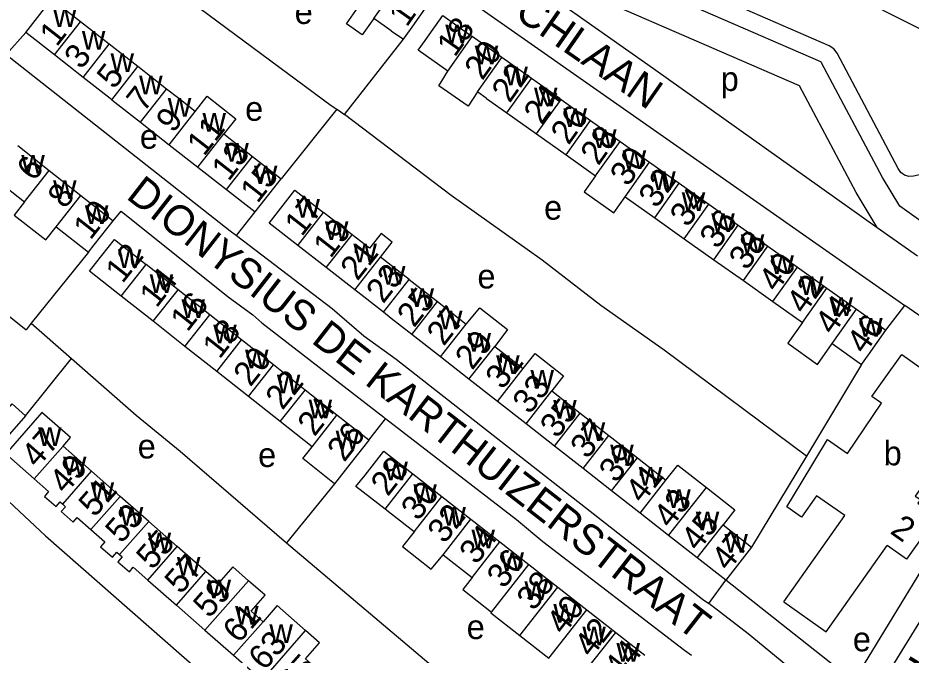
# Model space of a CAD drawing. Extents: x 162804 to 165059, y 381530 to 382901.
# Drawn here: x 162938.5 to 163085.6, y 381908.3 to 382013.3 of the extents above; entities that cross this region are included whole.
import ezdxf

# ---------------------------------------------------------------- set-up
doc = ezdxf.new("R2010")
doc.units = 0
for name, color, linetype in [('BLT_Basislijn', 7, 'Continuous'), ('BLT_Bebouwing', 7, 'Continuous'), ('BLT_Centroide', 7, 'Continuous'), ('BLT_Huisnummer', 7, 'Continuous'), ('BLT_Huisnummer_ tussenligend', 7, 'Continuous'), ('BLT_Onderverdeling_panden', 7, 'Continuous'), ('BLT_Straatnaam', 7, 'Continuous')]:
    doc.layers.add(name, color=color, linetype=linetype)

msp = doc.modelspace()

# ---------------------------------------------------------------- linework, layer by layer
at = {"layer": 'BLT_Basislijn'}
for p, q in [((163017.7, 382022.93), (163043.15, 382004.93)), ((162939.82, 382010.89), (162936.61, 382007.27)), ((162992.27, 381997.38), (163002.01, 382009.76)), ((162991.04, 381998.28), (162981.87, 381986.8)), ((162974.48, 381977.48), (162977.59, 381981.33)), ((162950.13, 381974.7), (162940.71, 381963)), ((163081.43, 381961.88), (163084.55, 381965.91)), ((163104.58, 381951.95), (163084.55, 381965.91)), ((162940.71, 381963), (162939.87, 381961.94)), ((162939.79, 381947.76), (162947.33, 381957.19)), ((163077.42, 381956.21), (163068.32, 381941.11)), ((162996.28, 381943.74), (162999.06, 381947.28)), ((163068.32, 381941.11), (163059.3, 381926.12)), ((162990.63, 381936.58), (162982.74, 381926.86)), ((162982.74, 381926.86), (163031.79, 381885.39)), ((163052.24, 381916.83), (163055.05, 381920.69))]:
    msp.add_line(p, q, dxfattribs=at)
for points in [[(163069.06, 382020.59), (163092.61, 382008.67), (163093.4, 382008.13), (163093.97, 382007.5), (163094.42, 382006.7), (163094.66, 382005.84), (163095.46, 381992), (163095.33, 381990.1), (163094.6, 381989.08), (163085.95, 381987.21), (163085.18, 381987.15), (163084.46, 381987.37), (163083.85, 381987.84), (163083.46, 381988.49), (163073.39, 382007.47), (163072.87, 382008.21), (163072.1, 382008.69), (163021.58, 382030.69)], [(163083.72, 381982.26), (163080.85, 381987.02), (163070.82, 382005.91), (163070.76, 382005.99), (163070.7, 382006.03), (163017.52, 382029.19)], [(162952.58, 382027.08), (162967.07, 382015.96), (162990.08, 381998.88), (162991.04, 381998.28)], [(163079.98, 381978.78), (163076.5, 381984.55), (163067.17, 382002.11), (163018.09, 382023.48), (163017.7, 382022.93)], [(163008.76, 382019.07), (163083.58, 381966.59), (163084.55, 381965.91)], [(162936.61, 382007.27), (162973.48, 381978.24), (162974.48, 381977.48)], [(163043.15, 382004.93), (163079.98, 381978.78)], [(162991.04, 381998.28), (162991.3, 381998.11), (162992.27, 381997.38)], [(163068.32, 381941.11), (163044.93, 381958.57), (163034.48, 381965.9), (163024.84, 381973.39), (163009.83, 381984.04), (162992.27, 381997.38)], [(162913.43, 381984.1), (162927.71, 381972.16), (162934.84, 381965.92), (162939.87, 381961.94)], [(162954.2, 381979.85), (162955.5, 381981.48), (162973.11, 381967.38), (162977.21, 381964.39), (162978.7, 381963.05), (162998.74, 381947.53), (162999.06, 381947.28)], [(163088.69, 381978.74), (163083.72, 381982.26)], [(163079.98, 381978.78), (163086.6, 381974.08)], [(162974.48, 381977.48), (162990.26, 381965.42), (162995.48, 381960.92), (163000.81, 381957.09), (163051.25, 381917.58), (163052.24, 381916.83)], [(162940.71, 381963), (162946.88, 381957.58), (162947.33, 381957.19)], [(162947.33, 381957.19), (162957.97, 381947.89), (162965.23, 381941.96), (162982.74, 381926.86)], [(163104.58, 381951.95), (163107.72, 381949.86), (163108.33, 381948.97), (163107.96, 381947.96), (163081.42, 381904.82), (163078.3, 381900.84), (163076.07, 381900.06), (163074.79, 381900.06), (163072.4, 381900.61), (163058.73, 381911.86), (163052.24, 381916.83)], [(163104.58, 381951.95), (163102.76, 381948.29), (163098.1, 381940.15), (163076.45, 381904.65), (163075.65, 381904.65), (163073.11, 381906.41), (163055.05, 381920.69)], [(163049.39, 381908.29), (163048.27, 381909.14), (163024.93, 381927.03), (163020.58, 381930.61), (162999.06, 381947.28)], [(162933.29, 381940.41), (162931.69, 381938.6), (162943.06, 381927.99), (162971.29, 381903.26), (162975.18, 381899.34), (162996.37, 381880.88), (163016.11, 381863.18), (163017.03, 381862.36)]]:
    msp.add_lwpolyline(points, dxfattribs=at)
at = {"layer": 'BLT_Bebouwing'}
for p, q in [((162948.82, 382012.66), (162944.09, 382016.36)), ((162953.54, 382008.97), (162948.82, 382012.66)), ((162999.99, 382011.17), (162997.11, 382013.21)), ((162944.54, 382007.19), (162939.82, 382010.89)), ((162999.99, 382011.17), (163002.01, 382009.76)), ((163018.19, 382006.77), (163013.32, 382010.22)), ((162958.26, 382005.27), (162953.54, 382008.97)), ((162949.26, 382003.5), (162944.54, 382007.19)), ((163023.06, 382003.32), (163018.19, 382006.77)), ((162962.99, 382001.58), (162958.26, 382005.27)), ((163027.72, 382000.02), (163023.06, 382003.32)), ((163015.68, 382000.01), (163014.16, 382001.09)), ((162953.98, 381999.8), (162958.71, 381996.11)), ((163015.68, 382000.01), (163019.03, 381997.64)), ((163027.72, 382000.02), (163027.93, 381999.87)), ((163027.93, 381999.87), (163032.79, 381996.42)), ((163019.03, 381997.64), (163023.89, 381994.18)), ((162958.71, 381996.11), (162963.43, 381992.41)), ((163032.79, 381996.42), (163037.66, 381992.96)), ((162972.43, 381994.19), (162977.15, 381990.49)), ((163023.89, 381994.18), (163028.76, 381990.73)), ((162938.49, 381992.25), (162943.69, 381988.14)), ((162963.43, 381992.41), (162968.15, 381988.72)), ((163037.66, 381992.96), (163042.52, 381989.51)), ((162977.15, 381990.49), (162981.87, 381986.8)), ((163028.76, 381990.73), (163033.63, 381987.28)), ((162968.15, 381988.72), (162972.88, 381985.02)), ((163042.52, 381989.51), (163047.39, 381986.05)), ((162934.42, 381987.1), (162939.63, 381982.99)), ((162943.69, 381988.14), (162948.87, 381984.05)), ((163047.39, 381986.05), (163052.25, 381982.6)), ((162972.88, 381985.02), (162977.59, 381981.33)), ((162948.87, 381984.05), (162954.2, 381979.85)), ((163038.49, 381983.83), (163043.36, 381980.38)), ((162993.53, 381977.59), (162988.83, 381981.26)), ((163052.25, 381982.6), (163057.12, 381979.15)), ((163043.36, 381980.38), (163048.23, 381976.92)), ((162944.81, 381978.9), (162950.13, 381974.7)), ((163057.12, 381979.15), (163061.98, 381975.69)), ((163048.23, 381976.92), (163053.09, 381973.47)), ((162989.28, 381972.16), (162984.58, 381975.83)), ((163061.98, 381975.69), (163066.85, 381972.24)), ((162964.88, 381968.53), (162959.65, 381972.66)), ((163053.09, 381973.47), (163057.96, 381970.02)), ((162993.98, 381968.48), (162989.28, 381972.16)), ((163066.85, 381972.24), (163071.71, 381968.78)), ((163002.92, 381970.23), (163007.62, 381966.56)), ((163057.96, 381970.02), (163062.82, 381966.57)), ((162970.11, 381964.4), (162964.88, 381968.53)), ((162998.68, 381964.81), (162993.98, 381968.48)), ((163071.71, 381968.78), (163076.57, 381965.33)), ((162960.78, 381963.33), (162955.54, 381967.47)), ((163007.62, 381966.56), (163012.32, 381962.88)), ((163062.82, 381966.57), (163067.69, 381963.11)), ((163076.57, 381965.33), (163081.43, 381961.88)), ((162975.35, 381960.27), (162970.11, 381964.4)), ((162966.01, 381959.2), (162960.78, 381963.33)), ((163008.07, 381957.45), (163003.38, 381961.13)), ((162971.25, 381955.07), (162966.01, 381959.2)), ((162980.58, 381956.13), (162975.35, 381960.27)), ((163017.02, 381959.2), (163021.71, 381955.53)), ((163072.56, 381959.66), (163077.42, 381956.21)), ((163012.77, 381953.78), (163008.07, 381957.45)), ((162976.48, 381950.94), (162971.25, 381955.07)), ((162985.82, 381952), (162980.58, 381956.13)), ((163017.47, 381950.1), (163012.77, 381953.78)), ((162991.05, 381947.87), (162985.82, 381952)), ((163026.41, 381951.85), (163031.11, 381948.18)), ((162981.71, 381946.81), (162976.48, 381950.94)), ((163022.17, 381946.43), (163017.47, 381950.1)), ((162996.28, 381943.74), (162991.05, 381947.87)), ((163031.11, 381948.18), (163035.81, 381944.5)), ((162986.95, 381942.67), (162981.71, 381946.81)), ((163026.86, 381942.75), (163022.17, 381946.43)), ((163035.81, 381944.5), (163040.51, 381940.82)), ((162950.65, 381938.62), (162945.95, 381942.75)), ((163031.56, 381939.07), (163026.86, 381942.75)), ((163040.51, 381940.82), (163045.2, 381937.15)), ((162955.35, 381934.49), (162950.65, 381938.62)), ((163036.26, 381935.4), (163031.56, 381939.07)), ((163003.53, 381938.21), (163008.3, 381934.48)), ((162960.06, 381930.37), (162955.35, 381934.49)), ((163008.3, 381934.48), (163013.08, 381930.74)), ((163040.96, 381931.72), (163036.26, 381935.4)), ((163045.65, 381928.04), (163040.96, 381931.72)), ((163064.63, 381917.13), (163074.68, 381931.32)), ((162964.76, 381926.24), (162960.06, 381930.37)), ((163013.08, 381930.74), (163017.86, 381927.01)), ((163054.6, 381929.8), (163059.3, 381926.12)), ((163017.86, 381927.01), (163022.64, 381923.27)), ((163050.35, 381924.37), (163045.65, 381928.04)), ((162969.46, 381922.11), (162964.76, 381926.24)), ((163071.59, 381912.19), (163081.65, 381926.39)), ((163008.51, 381924.89), (163013.29, 381921.16)), ((163055.05, 381920.69), (163050.35, 381924.37)), ((163022.64, 381923.27), (163027.41, 381919.54)), ((162959.91, 381920.72), (162964.62, 381916.6)), ((163027.41, 381919.54), (163032.19, 381915.8)), ((162964.62, 381916.6), (162969.32, 381912.48)), ((163064.63, 381917.13), (163071.59, 381912.19)), ((163032.19, 381915.8), (163036.97, 381912.07)), ((162969.32, 381912.48), (162974.03, 381908.36)), ((163021.15, 381911.59), (163025.9, 381907.87)), ((163036.97, 381912.07), (163041.74, 381908.34)), ((162974.03, 381908.36), (162978.74, 381904.24))]:
    msp.add_line(p, q, dxfattribs=at)
for points in [[(162997.11, 382013.21), (162995.2, 382010.52), (162992.64, 382012.33), (162994.55, 382015.03), (162992.21, 382016.68)], [(162939.82, 382010.89), (162942.9, 382014.82), (162944.09, 382016.36)], [(163002.01, 382009.76), (163003.14, 382011.36), (163006.03, 382015.43)], [(163009.29, 382004.54), (163004.42, 382007.98), (163005.56, 382009.59), (163008.45, 382013.67), (163013.32, 382010.22)], [(162953.98, 381999.8), (162953.73, 382000), (162949.26, 382003.5)], [(163014.16, 382001.09), (163012.62, 381998.73), (163007.83, 382002.12), (163009.29, 382004.54)], [(162967.71, 381997.88), (162964.99, 382000.01), (162962.99, 382001.58)], [(162967.71, 381997.88), (162969.66, 382000.39), (162974.37, 381996.65), (162972.43, 381994.19)], [(163033.63, 381987.28), (163031.77, 381984.66), (163036.64, 381981.21), (163038.49, 381983.83)], [(162977.59, 381981.33), (162980.68, 381985.27), (162981.87, 381986.8)], [(162984.58, 381975.83), (162979.89, 381979.51), (162982.97, 381983.45), (162984.13, 381984.94), (162988.83, 381981.26)], [(162939.63, 381982.99), (162937.92, 381980.83), (162943.1, 381976.74), (162944.81, 381978.9)], [(162950.13, 381974.7), (162951.1, 381975.93), (162954.2, 381979.85)], [(162998.23, 381973.91), (163000.16, 381976.37), (162998.31, 381977.81), (162996.39, 381975.35), (162993.53, 381977.59)], [(162955.54, 381967.47), (162950.31, 381971.6), (162951.31, 381972.87), (162954.41, 381976.79), (162959.65, 381972.66)], [(163002.92, 381970.23), (162999.98, 381972.54), (162998.23, 381973.91)], [(163012.32, 381962.88), (163014.59, 381965.53), (163019.1, 381962), (163017.02, 381959.2)], [(163003.38, 381961.13), (162999.99, 381963.78), (162998.68, 381964.81)], [(163067.69, 381963.11), (163065.28, 381959.72), (163070.13, 381956.23), (163072.56, 381959.66)], [(163077.42, 381956.21), (163078.54, 381957.8), (163081.43, 381961.88)], [(163021.71, 381955.53), (163023.66, 381958.03), (163028.36, 381954.36), (163026.41, 381951.85)], [(163081.13, 381953.8), (163084.02, 381957.88), (163099.49, 381946.89), (163094.58, 381939.99), (163089.01, 381943.94), (163088.04, 381942.58), (163090.27, 381940.19), (163086.26, 381934.55), (163087.11, 381933.96), (163086.69, 381933.37), (163089.8, 381931.17), (163084.81, 381924.15), (163081.65, 381926.39)], [(163074.68, 381931.32), (163070.01, 381934.58), (163067.52, 381931.08), (163065.11, 381932.79), (163067.47, 381936.68), (163071.81, 381943.85), (163075.07, 381941.54), (163080.69, 381949.83), (163079.11, 381950.95), (163081.13, 381953.8)], [(162933.17, 381950.2), (162934.21, 381951.4), (162936.96, 381949.01), (162937.58, 381949.71), (162939.79, 381947.76)], [(162939.79, 381947.76), (162933.29, 381940.41)], [(162945.95, 381942.75), (162947.17, 381944.21), (162942.47, 381948.29), (162936.51, 381941.48), (162941.21, 381937.36)], [(162996.28, 381943.74), (162993.19, 381939.82), (162990.63, 381936.58)], [(162990.63, 381936.58), (162985.41, 381940.72), (162986.95, 381942.67)], [(162998.96, 381932.36), (162994.18, 381936.1), (162995.67, 381938.01), (162998.75, 381941.94), (163000, 381940.97), (163003.53, 381938.21)], [(163045.2, 381937.15), (163047.16, 381939.64), (163051.86, 381935.97)], [(162941.21, 381937.36), (162943.58, 381935.29), (162942.88, 381934.49), (162944.8, 381932.81), (162945.46, 381933.57), (162945.89, 381933.2)], [(163051.86, 381935.97), (163056.55, 381932.29), (163054.6, 381929.8)], [(162945.89, 381933.2), (162946.35, 381932.79), (162945.65, 381931.99), (162947.64, 381930.24), (162948.3, 381930.99), (162950.55, 381929.02)], [(163003.73, 381928.63), (163000.01, 381931.54), (162998.96, 381932.36)], [(162950.55, 381929.02), (162952.84, 381927.01), (162952.14, 381926.21), (162954.1, 381924.49), (162954.82, 381925.3), (162955.26, 381924.91)], [(163003.73, 381928.63), (163001.82, 381926.24), (163006.57, 381922.52), (163008.51, 381924.89)], [(163059.3, 381926.12), (163058.13, 381924.63), (163055.05, 381920.69)], [(162955.26, 381924.91), (162955.7, 381924.53), (162954.99, 381923.72), (162956.87, 381922.07), (162957.52, 381922.81), (162959.91, 381920.72)], [(162976.5, 381920.61), (162973.9, 381922.89), (162971.59, 381920.26), (162969.46, 381922.11)], [(163013.29, 381921.16), (163011.76, 381919.15), (163016.5, 381915.43)], [(162978.87, 381913.86), (162976.94, 381915.57), (162979.25, 381918.2), (162976.5, 381920.61)], [(162985.88, 381912.39), (162981.19, 381916.5), (162978.87, 381913.86)], [(163016.5, 381915.43), (163016.4, 381915.3), (163021.15, 381911.59)], [(162988.27, 381905.61), (162985.88, 381907.74), (162988.19, 381910.38), (162985.88, 381912.39)]]:
    msp.add_lwpolyline(points, dxfattribs=at)
at = {"layer": 'BLT_Onderverdeling_panden'}
for p, q in [((162997.11, 382013.21), (163001.14, 382018.9)), ((162944.54, 382007.19), (162948.82, 382012.66)), ((163009.29, 382004.54), (163013.32, 382010.22)), ((162949.26, 382003.5), (162953.54, 382008.97)), ((163014.16, 382001.09), (163018.19, 382006.77)), ((162953.98, 381999.8), (162958.26, 382005.27)), ((163019.03, 381997.64), (163023.06, 382003.32)), ((162958.71, 381996.11), (162962.99, 382001.58)), ((163023.89, 381994.18), (163027.93, 381999.87)), ((162963.43, 381992.41), (162967.71, 381997.88)), ((163028.76, 381990.73), (163032.79, 381996.42)), ((162968.15, 381988.72), (162972.43, 381994.19)), ((163033.63, 381987.28), (163037.66, 381992.96)), ((162972.88, 381985.02), (162977.15, 381990.49)), ((163038.49, 381983.83), (163042.52, 381989.51)), ((162939.63, 381982.99), (162943.69, 381988.14)), ((163043.36, 381980.38), (163047.39, 381986.05)), ((162944.81, 381978.9), (162948.87, 381984.05)), ((162984.58, 381975.83), (162988.83, 381981.26)), ((163048.23, 381976.92), (163052.25, 381982.6)), ((163053.09, 381973.47), (163057.12, 381979.15)), ((162989.28, 381972.16), (162993.53, 381977.59)), ((163057.96, 381970.02), (163061.98, 381975.69)), ((162993.98, 381968.48), (162998.23, 381973.91)), ((162955.54, 381967.47), (162959.65, 381972.66)), ((163062.82, 381966.57), (163066.85, 381972.24)), ((162998.68, 381964.81), (163002.92, 381970.23)), ((162960.78, 381963.33), (162964.88, 381968.53)), ((163067.69, 381963.11), (163071.71, 381968.78)), ((163003.38, 381961.13), (163007.62, 381966.56)), ((163072.56, 381959.66), (163076.57, 381965.33)), ((162966.01, 381959.2), (162970.11, 381964.4)), ((163008.07, 381957.45), (163012.32, 381962.88)), ((162971.25, 381955.07), (162975.35, 381960.27)), ((163012.77, 381953.78), (163017.02, 381959.2)), ((162976.48, 381950.94), (162980.58, 381956.13)), ((163017.47, 381950.1), (163021.71, 381955.53)), ((162981.71, 381946.81), (162985.82, 381952)), ((163022.17, 381946.43), (163026.41, 381951.85)), ((162986.95, 381942.67), (162991.05, 381947.87)), ((163026.86, 381942.75), (163031.11, 381948.18)), ((163031.56, 381939.07), (163035.81, 381944.5)), ((162941.21, 381937.36), (162945.95, 381942.75)), ((163036.26, 381935.4), (163040.51, 381940.82)), ((162945.89, 381933.2), (162950.65, 381938.62)), ((162998.96, 381932.36), (163003.53, 381938.21)), ((163040.96, 381931.72), (163045.2, 381937.15)), ((163045.65, 381928.04), (163051.86, 381935.97)), ((162950.55, 381929.02), (162955.35, 381934.49)), ((163003.73, 381928.63), (163008.3, 381934.48)), ((162955.26, 381924.91), (162960.06, 381930.37)), ((163008.51, 381924.89), (163013.08, 381930.74)), ((163050.35, 381924.37), (163054.6, 381929.8)), ((163013.29, 381921.16), (163017.86, 381927.01)), ((162959.91, 381920.72), (162964.76, 381926.24)), ((163016.5, 381915.43), (163022.64, 381923.27)), ((162964.62, 381916.6), (162969.46, 381922.11)), ((162969.32, 381912.48), (162976.5, 381920.61)), ((163021.15, 381911.59), (163027.41, 381919.54)), ((163025.9, 381907.87), (163032.19, 381915.8)), ((162974.03, 381908.36), (162978.87, 381913.86)), ((162978.74, 381904.24), (162985.88, 381912.39)), ((163030.65, 381904.16), (163036.97, 381912.07))]:
    msp.add_line(p, q, dxfattribs=at)

# ---------------------------------------------------------------- texts
at = {"layer": 'BLT_Centroide'}
for s, p in [('e', (162984.08, 382012.29)), ('w', (162944.31, 382011.78)), ('w', (163008.88, 382009.11)), ('w', (162949.05, 382008.08)), ('w', (163013.73, 382005.64)), ('w', (162953.77, 382004.38)), ('w', (163018.61, 382002.2)), ('w', (162958.48, 382000.69)), ('p', (163054.22, 382001.26)), ('w', (163023.48, 381998.75)), ('w', (162963.2, 381997)), ('e', (162975.93, 381996.35)), ('w', (162968.91, 381994.55)), ('w', (163028.34, 381995.31)), ('e', (162958.59, 381991.75)), ('w', (163033.2, 381991.84)), ('w', (162972.66, 381989.59)), ('w', (162939.08, 381987.62)), ('w', (163038.08, 381988.39)), ('w', (162977.38, 381985.91)), ('w', (163042.94, 381984.95)), ('w', (162944.31, 381983.47)), ('w', (163047.81, 381981.48)), ('w', (162984.36, 381980.38)), ('e', (163025.14, 381980.06)), ('w', (162949.55, 381979.34)), ('w', (162989.06, 381976.72)), ('w', (163052.67, 381978.05)), ('w', (163057.53, 381974.58)), ('w', (162993.75, 381973.03)), ('w', (162954.98, 381972.12)), ('w', (163062.41, 381971.14)), ('w', (162998.45, 381969.34)), ('w', (162960.21, 381968)), ('e', (163014.17, 381968.73)), ('w', (163067.27, 381967.67)), ('w', (163003.16, 381965.69)), ('w', (162965.45, 381963.88)), ('w', (163072.12, 381964.22)), ('w', (163007.84, 381962)), ('w', (163077, 381960.77)), ('w', (162970.68, 381959.72)), ('w', (163012.55, 381958.34)), ('w', (162975.91, 381955.59)), ('w', (163017.25, 381954.66)), ('w', (163022.91, 381952.22)), ('w', (162981.15, 381951.47)), ('w', (162986.38, 381947.34)), ('w', (163026.64, 381947.31)), ('w', (163031.34, 381943.62)), ('w', (162941.84, 381942.81)), ('w', (162990.84, 381942.23)), ('e', (162958.24, 381940.74)), ('w', (163036.03, 381939.94)), ('b', (163081.05, 381939.61)), ('e', (162978.06, 381939.33)), ('w', (162945.94, 381937.98)), ('w', (162998.86, 381937.16)), ('w', (163040.73, 381936.28)), ('w', (162950.5, 381933.75)), ('w', (163003.62, 381933.42)), ('w', (163045.42, 381932.59)), ('w', (162955.3, 381929.69)), ('w', (163008.41, 381929.69)), ('w', (163050.12, 381928.91)), ('w', (162959.88, 381925.45)), ('w', (163013.19, 381925.95)), ('w', (163054.83, 381925.25)), ('w', (162964.69, 381921.42)), ('w', (163017.97, 381922.22)), ('w', (162969.74, 381917.69)), ('w', (163021.91, 381917.44)), ('w', (163026.67, 381913.72)), ('w', (162974.28, 381913.38)), ('e', (163012.4, 381910.99)), ('w', (162979.92, 381910.33)), ('w', (163031.44, 381909.97)), ('e', (163075.97, 381908.98)), ('w', (163037.06, 381907.28))]:
    msp.add_text(s, height=4, dxfattribs=at).set_placement(p)
at = {"layer": 'BLT_Huisnummer'}
for s, rotation, p in [('16', 54.7141, (163002.53, 382011.64)), ('1', 51.9665, (162944.9, 382008.4)), ('18', 54.6553, (163010.44, 382006.68)), ('5', 51.9614, (162954.34, 382001.39)), ('22', 54.655, (163019.47, 381999.14)), ('26', 54.6564, (163029.18, 381992.21)), ('9', 51.9629, (162964.07, 381994.18)), ('30', 54.6566, (163038.95, 381985.35)), ('6', 51.7138, (162941.14, 381986.22)), ('15', 51.9522, (162977.96, 381982.61)), ('34', 54.6568, (163048.8, 381978.65)), ('10', 51.7179, (162950.46, 381976.58)), ('17', 51.9544, (162985.25, 381977.14)), ('38', 54.6571, (163058.52, 381971.55)), ('21', 51.9558, (162994.42, 381969.84)), ('14', 51.712, (162961.34, 381965.4)), ('42', 54.6981, (163067.99, 381964.32)), ('25', 51.9558, (163003.74, 381962.14)), ('46', 54.6129, (163077.9, 381957.75)), ('18', 51.7148, (162971.71, 381956.97)), ('29', 51.9558, (163013.31, 381955.14)), ('22', 51.7123, (162982.08, 381948.56)), ('33', 51.9572, (163022.77, 381947.85)), ('37', 51.9572, (163032.27, 381940.5)), ('26', 51.9937, (162992.25, 381940)), ('49', 48.7121, (162946.33, 381934.72)), ('41', 51.9572, (163041.34, 381933.16)), ('30', 51.9855, (163004.41, 381930.3)), ('53', 48.7046, (162955.56, 381926.59)), ('2', 324.6122, (163081.94, 381928.51)), ('34', 51.9881, (163014, 381923.1)), ('47', 51.9522, (163055.49, 381922.02)), ('57', 48.707, (162965.31, 381918.23)), ('38', 51.9908, (163023.44, 381915.48)), ('61', 48.7055, (162974.89, 381910.14)), ('42', 51.986, (163032.92, 381907.78)), ('65', 48.7093, (162984.13, 381901.82))]:
    msp.add_text(s, height=4, rotation=rotation, dxfattribs=at).set_placement(p)
at = {"layer": 'BLT_Huisnummer_ tussenligend'}
for s, rotation, p in [('20', 54.6553, (163014.98, 382002.85)), ('3', 51.9665, (162948.96, 382004.65)), ('7', 51.9614, (162959.23, 381997.61)), ('24', 54.655, (163024.74, 381995.55)), ('11', 51.9629, (162969.15, 381990.36)), ('28', 54.6564, (163034.08, 381988.82)), ('13', 51.9629, (162973.21, 381986.24)), ('32', 54.6566, (163043.66, 381981.77)), ('8', 51.7138, (162946.23, 381981.7)), ('36', 54.6568, (163053.7, 381975.06)), ('19', 51.9544, (162989.97, 381973.56)), ('12', 51.7179, (162955.74, 381969.42)), ('40', 54.6571, (163063.42, 381967.96)), ('23', 51.9558, (162998.66, 381966.09)), ('16', 51.712, (162966.43, 381961.44)), ('44', 54.6981, (163072.69, 381960.91)), ('27', 51.9558, (163008.63, 381959.11)), ('20', 51.7148, (162976.8, 381952.4)), ('31', 51.9558, (163018.3, 381951.92)), ('24', 51.7123, (162987.35, 381944.21)), ('35', 51.9572, (163027.29, 381943.89)), ('47', 48.7947, (162941.7, 381939.01)), ('39', 51.9572, (163036.99, 381936.55)), ('28', 51.9937, (162999.42, 381934.35)), ('51', 48.7121, (162951.15, 381930.91)), ('43', 51.9572, (163045.96, 381929.04)), ('32', 51.9855, (163008.76, 381926.54)), ('45', 51.9572, (163050.49, 381925.27)), ('55', 48.7046, (162960.65, 381922.25)), ('36', 51.9881, (163018.53, 381919.14)), ('59', 48.707, (162970.02, 381914.28)), ('40', 51.9908, (163028.33, 381911.51)), ('63', 48.7055, (162979.11, 381905.66)), ('44', 51.986, (163037.81, 381904.18))]:
    msp.add_text(s, height=4, rotation=rotation, dxfattribs=at).set_placement(p)
at = {"layer": 'BLT_Straatnaam'}
for s, rotation, p in [('HADEWYCHLAAN', 325.177, (162995.96, 382030.28)), ('DIONYSIUS DE KARTHUIZERSTRAAT', 322.0855, (162956.16, 381983.67)), ('ST LIDWINASTRAAT', 58.1784, (163083.63, 381895.69))]:
    msp.add_text(s, height=5, rotation=rotation, dxfattribs=at).set_placement(p)

doc.saveas('drawing.dxf')
